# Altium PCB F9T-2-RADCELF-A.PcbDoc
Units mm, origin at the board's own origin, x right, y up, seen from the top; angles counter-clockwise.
Board outline 67.17 x 37.33 mm, 2 copper layers (Top Layer, Bottom Layer), stack 1.581 mm thick; 13 components, 9 nets, 182 pads, 126 vias.
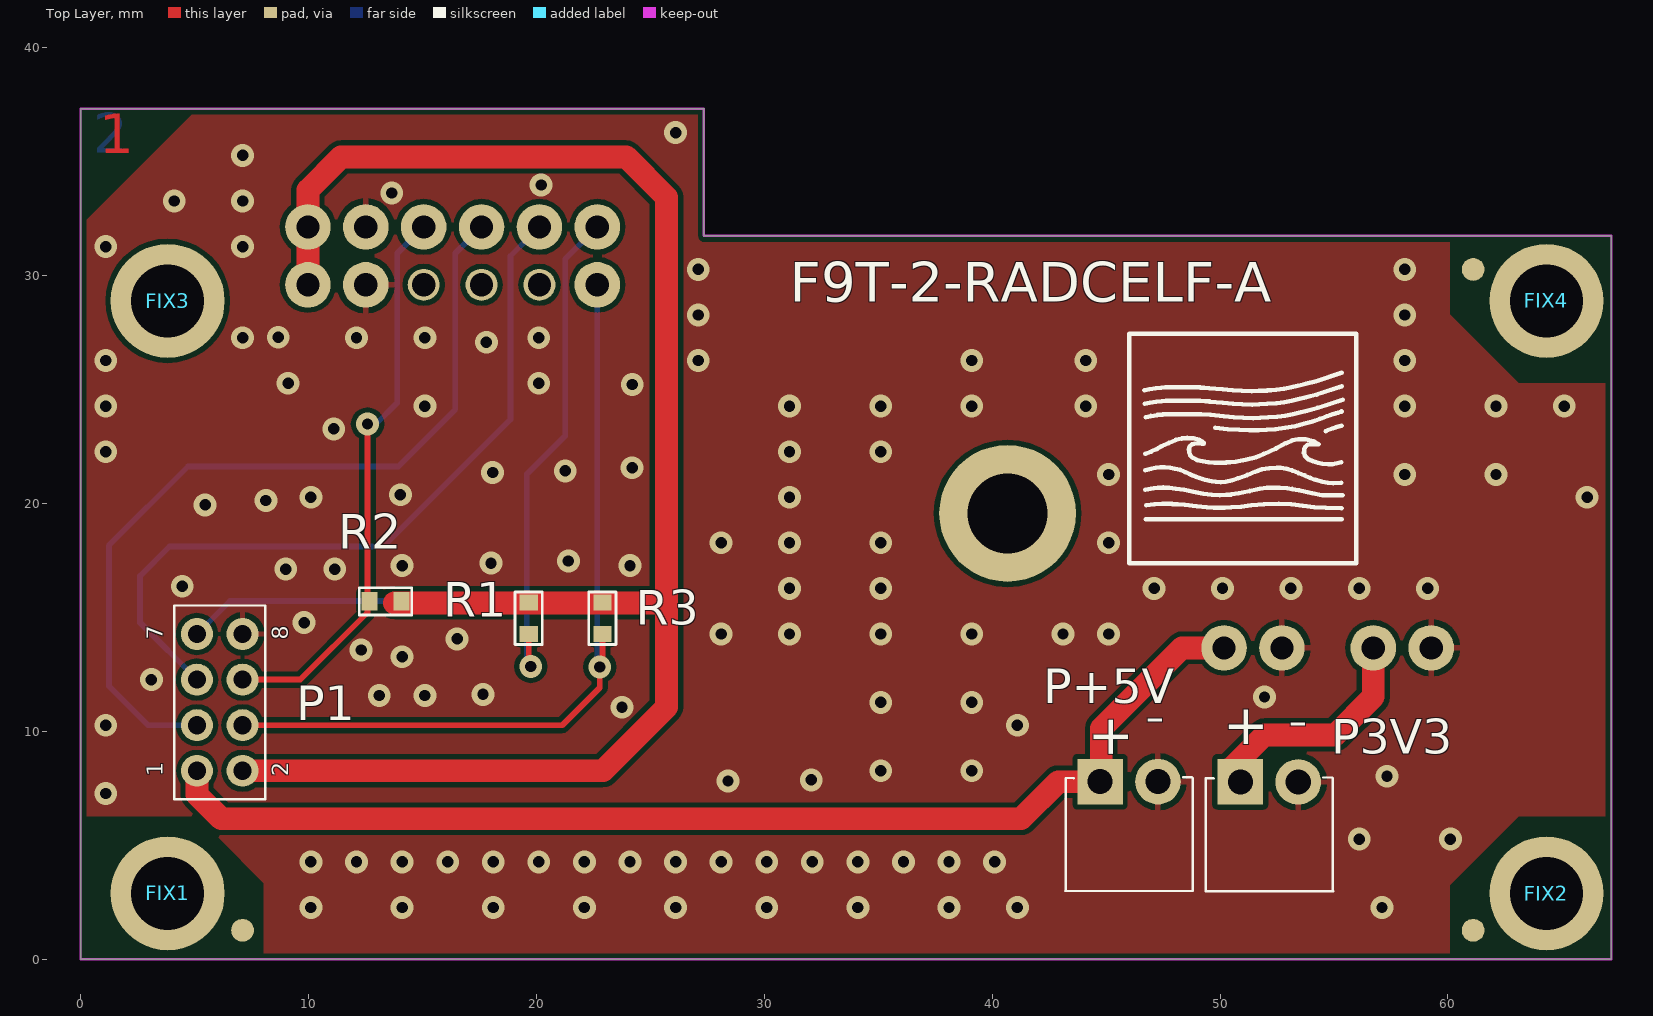
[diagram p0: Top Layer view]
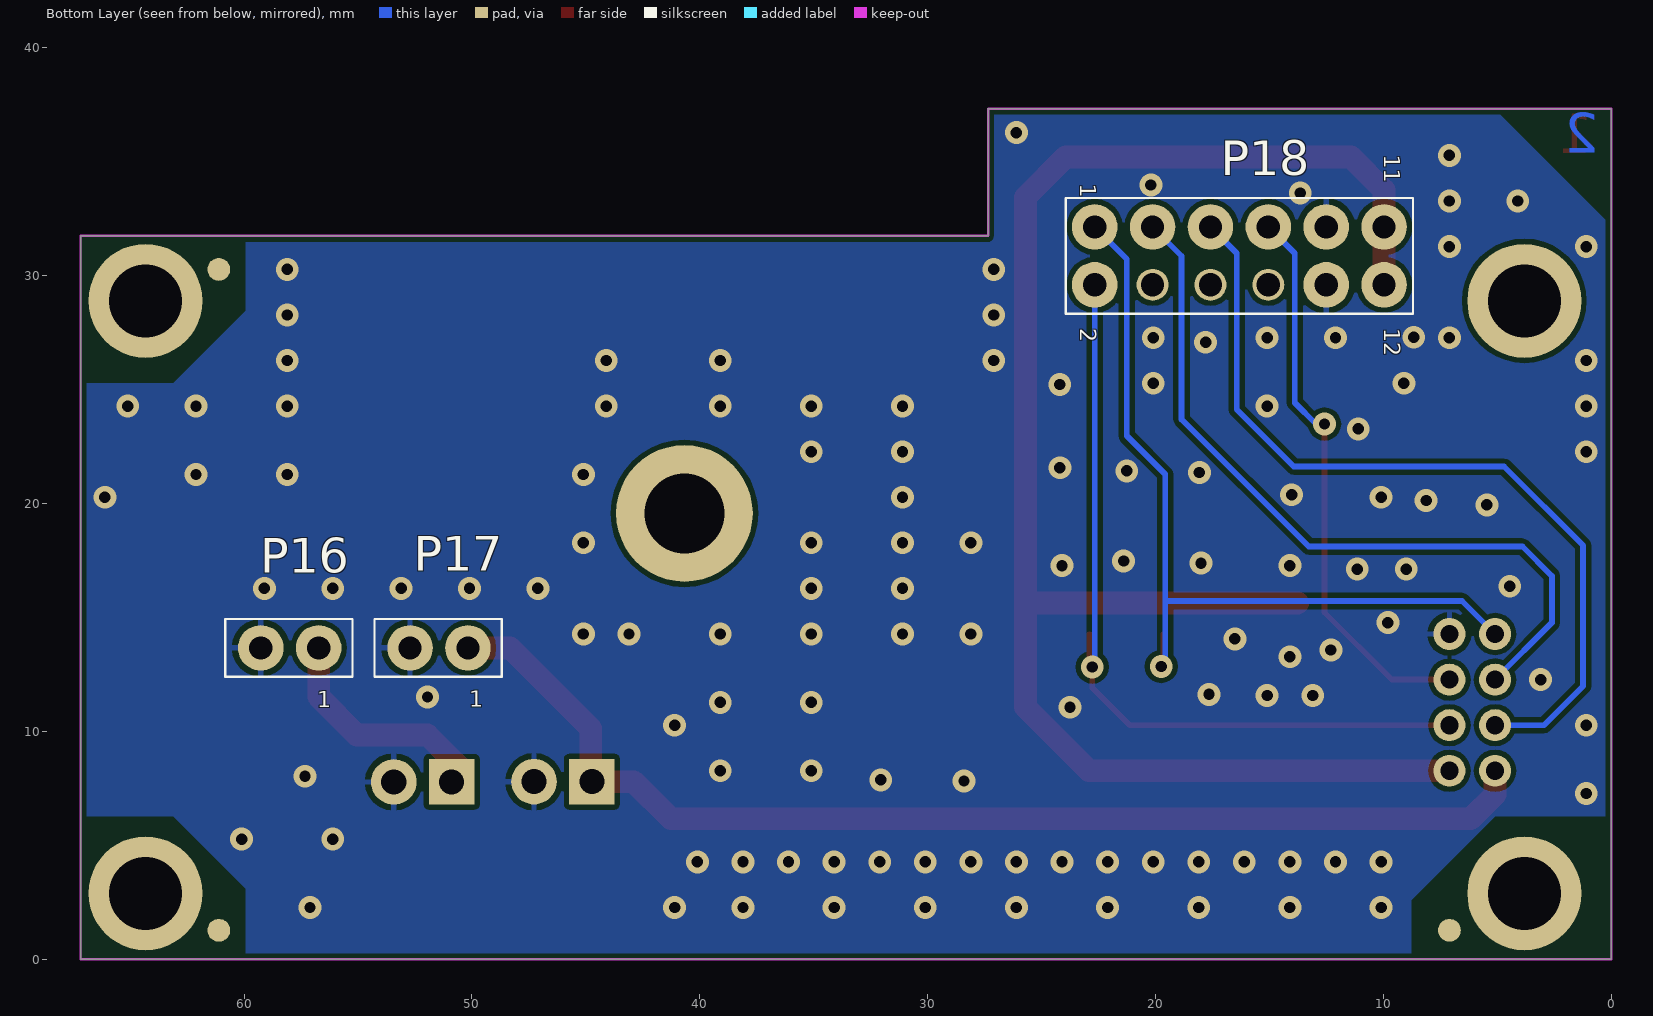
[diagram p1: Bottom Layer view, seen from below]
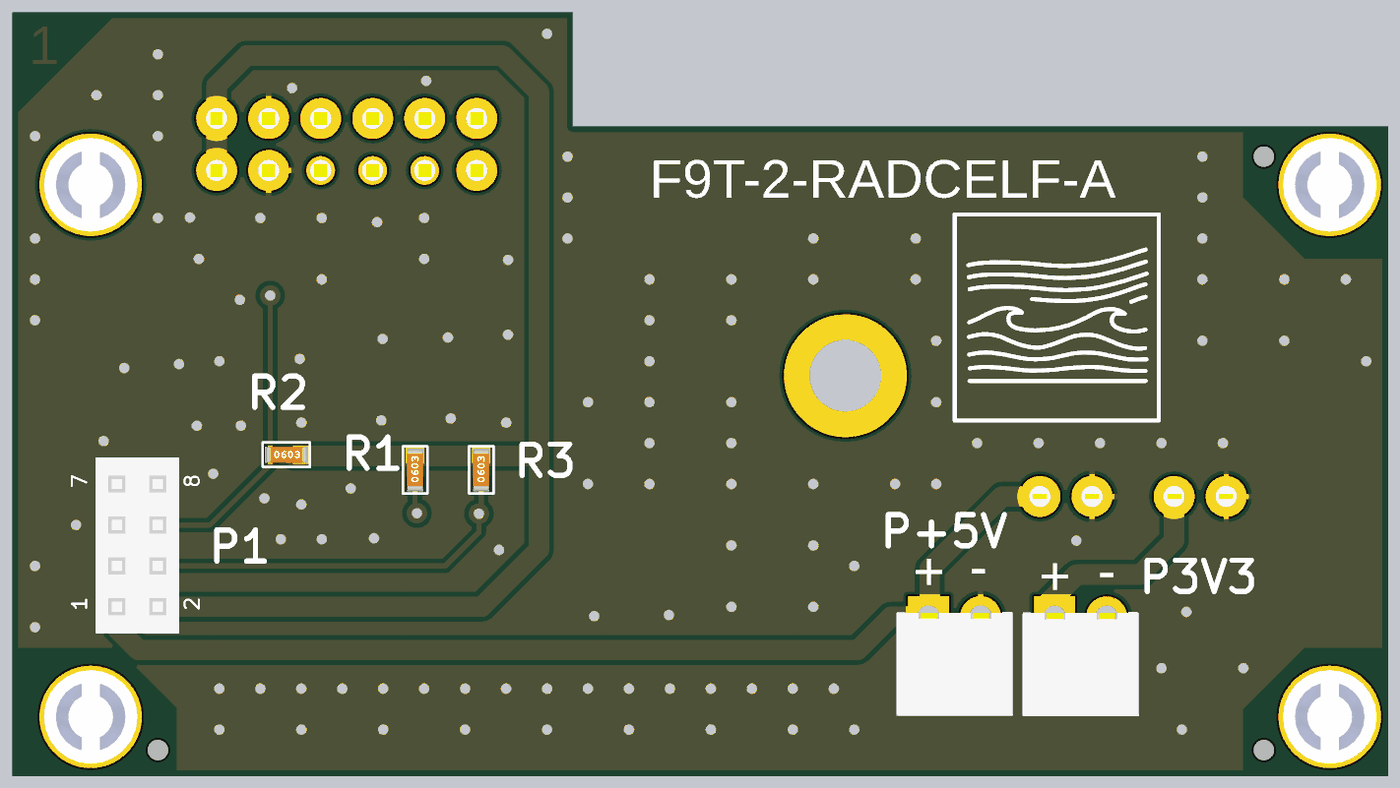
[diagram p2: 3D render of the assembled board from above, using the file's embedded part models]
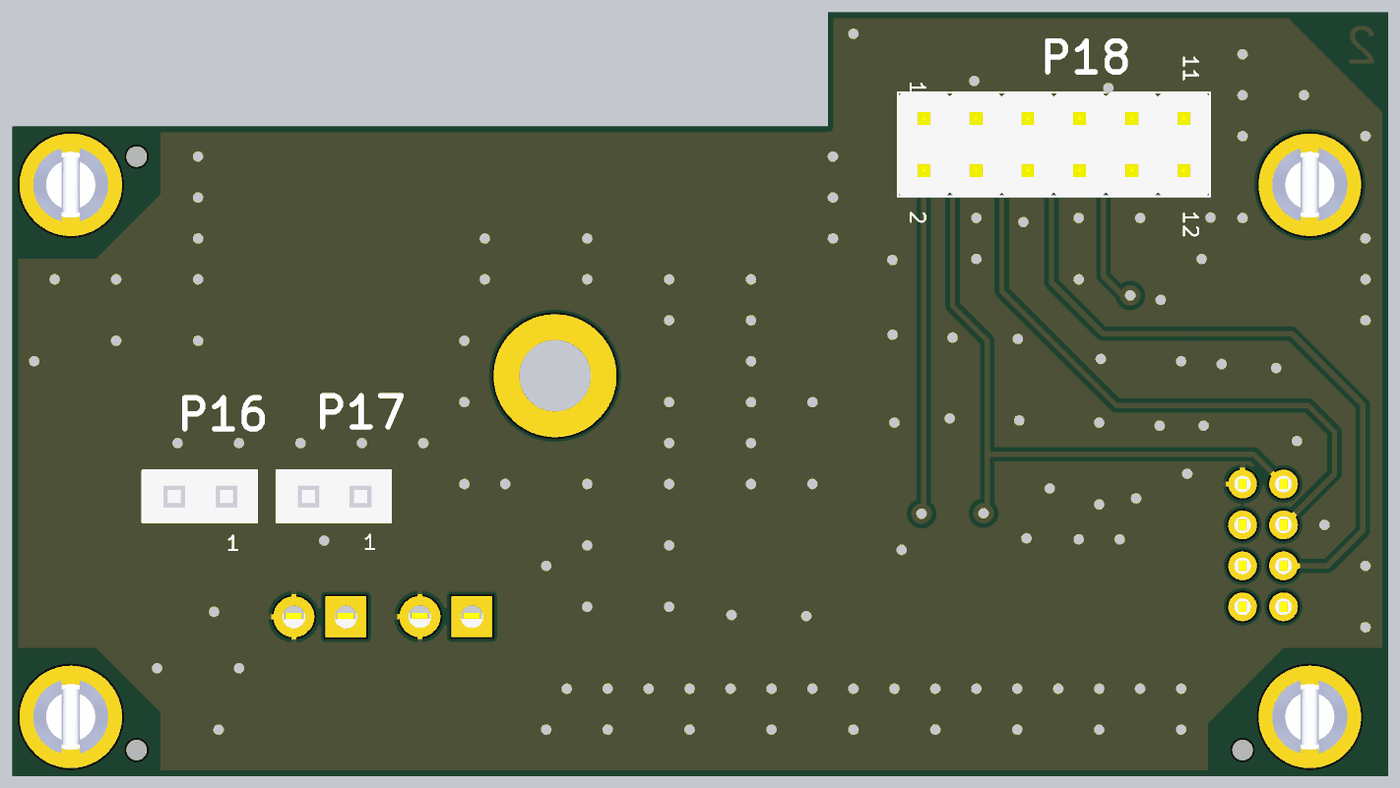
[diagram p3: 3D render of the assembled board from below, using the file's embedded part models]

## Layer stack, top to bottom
Top Solder: solder mask 0.0102, Solder Resist, Dk 3.5
Top Layer: signal copper 0.0356
Dielectric 1: dielectric 1.51, FR-4, Dk 4.8
Bottom Layer: signal copper 0.0356
Bottom Solder: solder mask 0.0102, Solder Resist, Dk 3.5

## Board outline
0,0 0,37.325 27.349,37.325 27.349,31.766 27.366,31.749 67.174,31.749 67.174,0

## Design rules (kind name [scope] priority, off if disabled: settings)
Clearance Clearance_1 [All] p1: gap=0.22 ignorepadtopadclearanceinfootprint=FALSE except(0: Arc-Hole Track-Hole SMDPad-Hole THPad-Hole Via-Hole Fill-Hole Poly-Hole Region-Hole Text-Hole)
Clearance [OnLayer('Keep-Out Layer')] p2: gap=0.4 ignorepadtopadclearanceinfootprint=FALSE except(0: Arc-Hole Track-Hole SMDPad-Hole THPad-Hole Via-Hole Fill-Hole Poly-Hole Region-Hole Text-Hole)
ComponentClearance [All] p1 off: gap=0.254 collisioncheckmode=3 verticalgap=0.254 showdistances=FALSE
Height [All] p1 off: minheight=0 maxheight=25.4 prefheight=12.7
HoleSize [All] p1: absolutevalues=TRUE maxlimit=10 minlimit=0.025 maxpercent=80.000 minpercent=20.000
MinimumSolderMaskSliver [All] p1 off: minsoldermaskwidth=0.254
PolygonConnect PolygonConnect_1 [IsVia] p1: connectstyle=Direct reliefconductorwidth=0.254 reliefentries=4 polygonreliefangle="90 Angle" airgapwidth=0.254
PolygonConnect [All] p2: connectstyle=Relief reliefconductorwidth=0.254 reliefentries=4 polygonreliefangle="90 Angle" airgapwidth=0.254
RoutingVias [All] p1: holewidth=0.711 width=1.27 viastyle="Through Hole" minholewidth=0.3 minwidth=0.7 maxholewidth=0.711 maxwidth=1.27
SilkToBoardRegionClearance [All] p1 off:
SilkToSilkClearance [All] p1 off: silktosilkclearance=0.254
SilkToSolderMaskClearance [IsPad] p1 off: minsilkscreentomaskgap=0.254 clearancetoexposedcopper=TRUE
SolderMaskExpansion [All] p1: expansion=0.102
Width [All] p1: maxlimit=10 minlimit=0.254 preferedwidth=0.254 minimp=50.000000 maximp=50.000000 favimp=50.000000
23 further rules are at their usual default settings.

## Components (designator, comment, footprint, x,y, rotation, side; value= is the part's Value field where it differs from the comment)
FIX1 "8882" 8882 3.823,2.896 r0 top
FIX2 "8882" 8882 64.323,2.896 r0 top
FIX3 "8882" 8882 3.823,28.896 r0 top
FIX4 "8882" 8882 64.323,28.896 r0 top
P1 "AF1D-200-08-G-H63" AF1D-200-08-G-H63 5.107,8.276 r90 top
P3V3 "AF1C-02-G-H5" AF1C-02-G-H5 50.889,7.784 r180 top
P16 "F1D-02-G" F1D-02-G 56.725,13.667 r0 bottom
P17 "" F1D-02-G 50.175,13.667 r0 bottom
P18 "A61-12-7-G" A61-12-7-G 16.324,30.868 r270 bottom locked
P+5V "AF1C-02-G-H5" AF1C-02-G-H5 44.735,7.796 r180 top
R1 "4.7K" 0603 19.662,14.966 r90 top
R2 "4.7K" 0603 13.381,15.711 r0 top
R3 "4.7K" 0603 22.895,14.966 r90 top

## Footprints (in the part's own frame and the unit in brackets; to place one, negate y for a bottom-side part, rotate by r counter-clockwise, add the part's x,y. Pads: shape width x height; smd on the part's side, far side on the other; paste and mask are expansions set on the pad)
0603 [mm]
  rect 0.7x0.8 smd mask+0.05: 1(-0.7,0) 2(0.7,0)
  silkscreen extent -1.15,-0.6 1.15,0.6, body extent -1,-0.39 1,0.39, height 0.79
8882 [mm]
  round 5 hole 3.2: FIX(0,0)
  body extent -2.29,-2.29 2.29,2.29, height 13.29
A61-12-7-G [mm]
  round 2 hole 1.02: 1(-1.27,-6.35) 2(1.27,-6.35) 3(-1.27,-3.81) 5(-1.27,-1.27) 7(-1.27,1.27) 9(1.27,3.81) 10(-1.27,3.81) 11(1.27,6.35) 12(-1.27,6.35)
  round 1.4 hole 1.02: 4(1.27,-3.81) 6(1.27,-1.27) 8(1.27,1.27)
  silkscreen extent -2.54,-7.62 2.54,7.62, body extent -2.54,-7.62 2.54,7.62, height 9.54
AF1C-02-G-H5 [mm]
  rect 2x2 hole 1.1: 1(0,0)
  round 2 hole 1.1: 2(-2.54,0)
  silkscreen extent -4.08,-0.19 1.53,4.8, body extent -4.08,-0.19 1.5,4.81, height 2.6
AF1D-200-08-G-H63 [mm]
  round 1.4 hole 0.8: 1(0,0) 2(0,-2) 3(2,0) 4(2,-2) 5(4,0) 6(4,-2) 7(6,0) 8(6,-2)
  silkscreen extent -1.25,-3 7.25,1, body extent -1.2,-3 7.2,1, height 6.35
F1D-02-G [mm]
  round 2 hole 1.02: 1(0,0) 2(2.54,0)
  silkscreen extent -1.49,-1.27 4.1,1.27, body extent -1.52,-1.27 4.06,1.27, height 5

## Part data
FIX1 FIX2 FIX3 FIX4: library part CON1, "Connector", Manufacturer 1=KEYSTONE
P1: library part CON8, "Connector", Manufacturer 1=ANTELEC
P3V3 P16 P+5V: library part CON2, "Connector", Manufacturer 1=ANTELEC
P17: library part CON2, "Connector", Manufacturer 1=ANTELEC, Manufacturer Part Number 1=F1D-02-G
P18: library part CON12, "Connector", Manufacturer 1=ANTELEC
R1 R2 R3: library part 0805R, "RES SMD 4.7K 1% 1/5W 0603"

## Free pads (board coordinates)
  rect 0.813x0.813 on Mech16: 1(9.212,25.417) 1(10.736,25.417) 1(13.464,25.468) 1(14.988,25.468) 1(18.561,19.268) 1(20.085,19.268) 1(22.813,19.316) 1(24.337,19.316) 1(25.912,29.766) 1(25.912,31.267) 1(25.912,32.768) 1(27.436,29.766) 1(27.436,31.267) 1(27.436,32.768) 1(27.624,26.055) 1(27.624,27.579) 1(35.112,21.468) 1(35.112,22.966) 1(36.062,30.017) 1(36.636,21.468) 1(36.636,22.966) 1(37.586,30.017) 1(39.062,25.217) 1(40.586,25.217)
  rect 1.499x0.45 on Mech16: 1(9.224,19.593) 1(9.224,20.241) 1(9.224,20.891) 1(9.224,21.541) 1(9.224,22.192) 1(9.224,22.842) 1(9.224,23.492) 1(9.224,24.142) 1(15.026,19.593) 1(15.026,20.241) 1(15.026,20.891) 1(15.026,21.541) 1(15.026,22.192) 1(15.026,22.842) 1(15.026,23.492) 1(15.026,24.142) 1(18.523,20.591) 1(18.523,21.242) 1(18.523,21.892) 1(18.523,22.542) 1(18.523,23.192) 1(18.523,23.843) 1(18.523,24.493) 1(18.523,25.143) 1(24.325,20.591) 1(24.325,21.242) 1(24.325,21.892) 1(24.325,22.542) 1(24.325,23.192) 1(24.325,23.843) 1(24.325,24.493) 1(24.325,25.143)
  rect 1.016x1.999 on Mech16: 1(9.974,27.967) 1(9.974,33.766) 1(12.514,27.967) 1(12.514,33.766) 1(15.054,27.967) 1(15.054,33.766) 1(17.594,27.967) 1(17.594,33.766) 1(20.134,27.967) 1(20.134,33.766) 1(22.674,27.967) 1(22.674,33.766)
  round 0.991 on Mech16: 1(11.244,30.868) 1(16.324,30.868) 1(21.404,30.868)
  rect 1.016x1.016 on Mech16: 1(25.584,34.414) 1(25.584,36.319) 1(31.284,21.214) 1(31.284,23.121)
  rect 1.372x1.016 on Mech16: 1(27.616,35.367) 1(33.316,22.166)
  rect 0.399x0.95 on Mech16: 1(29.074,27.518) 1(29.074,29.718) 1(29.725,27.518) 1(29.725,29.718) 1(30.375,27.518) 1(30.375,29.718) 1(39.173,27.416) 1(39.173,29.616) 1(39.824,27.416) 1(39.824,29.616) 1(40.474,27.416) 1(40.474,29.616)
  round 2.54 on Mech16: 1(31.284,33.177) 1(31.284,38.257) 1(33.824,35.717) 1(36.364,33.177) 1(36.364,38.257) 1(41.383,33.078) 1(41.383,38.158) 1(43.923,35.618) 1(46.463,33.078) 1(46.463,38.158) 1(49.585,33.078) 1(49.585,38.158) 1(52.125,35.618) 1(54.665,33.078) 1(54.665,38.158) 1(58.084,33.078) 1(58.084,38.158) 1(60.624,35.618) 1(63.164,33.078) 1(63.164,38.158)
  rect 1.049x2.2 on Mech16: 1(32.348,26.517) 1(35.3,26.517) 1(42.45,26.418) 1(45.399,26.418) 1(50.649,26.418) 1(53.601,26.418) 1(59.151,26.418) 1(62.1,26.418)
  rect 1.148x1.798 on Mech16: 1(33.674,17.767) 1(36.674,17.767)
  rect 0.998x1.049 on Mech16: 1(33.824,28.041) 1(43.923,27.942) 1(52.125,27.942) 1(60.624,27.942)
  rect 1.016x0.864 on Mech16: 1(33.824,29.806) 1(33.824,31.229) 1(43.923,29.705) 1(43.923,31.127) 1(52.125,29.705) 1(52.125,31.127) 1(60.624,29.705) 1(60.624,31.127)
  round 5.791 on Mech16: 1(40.675,19.568)
  rect 1.524x1.524 on Mech16: 1(50.174,13.667) 1(56.725,13.667)
  round 1.524 on Mech16: 1(52.714,13.667) 1(59.265,13.667)
  round 3.198 on Mech16: 1(63.674,14.066)
  round 6 hole 3.5: fix(40.675,19.567)
  round 1 smd mask+0.1: MIRE(7.107,1.276) MIRE(61.107,1.276) MIRE(61.107,30.276)
  round 1 smd far side mask+0.1: MIRE(7.107,1.276) MIRE(61.107,1.276) MIRE(61.107,30.276)

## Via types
v1: diameter 1, hole 0.5, Top Layer to Bottom Layer, 126 vias

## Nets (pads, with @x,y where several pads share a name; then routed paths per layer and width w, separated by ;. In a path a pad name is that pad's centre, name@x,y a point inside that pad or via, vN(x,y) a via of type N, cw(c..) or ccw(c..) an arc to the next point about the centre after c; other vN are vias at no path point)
0VD: P1.8 P3V3.2 P16.2 P17.2 P18.9 P18.10 P+5V.2
  other v1: 10.107,2.276 14.107,2.276 18.107,2.276 22.107,2.276 26.107,2.276 30.107,2.276 34.107,2.276 38.107,2.276 41.107,2.276 57.107,2.276 10.107,4.276 12.107,4.276 14.107,4.276 16.107,4.276 18.107,4.276 20.107,4.276 22.107,4.276 24.107,4.276 26.107,4.276 28.107,4.276 30.107,4.276 32.107,4.276 34.107,4.276 36.107,4.276 38.107,4.276 40.107,4.276 56.107,5.276 60.107,5.276 1.107,7.276 28.407,7.826 32.057,7.876 57.325,8.03 35.107,8.276 39.107,8.276 1.107,10.276 41.107,10.276 23.756,11.058 35.107,11.276 39.107,11.276 51.949,11.511 13.107,11.576 15.107,11.576 17.657,11.626 3.107,12.276 14.107,13.276 12.307,13.576 16.521,14.059 28.107,14.276 31.107,14.276 35.107,14.276 39.107,14.276 43.107,14.276 45.107,14.276 9.807,14.776 31.107,16.276 35.107,16.276 47.107,16.276 50.107,16.276 53.107,16.276 56.107,16.276 59.107,16.276 4.457,16.376 9.007,17.126 11.157,17.126 14.107,17.276 24.107,17.276 18.01,17.386 21.407,17.479 28.107,18.276 31.107,18.276 35.107,18.276 45.107,18.276 5.465,19.942 8.133,20.135 10.107,20.276 31.107,20.276 66.107,20.276 14.032,20.387 45.107,21.276 58.107,21.276 62.107,21.276 18.08,21.364 21.267,21.434 24.198,21.573 1.107,22.276 31.107,22.276 35.107,22.276 11.107,23.276 1.107,24.276 15.107,24.276 31.107,24.276 35.107,24.276 39.107,24.276 44.107,24.276 58.107,24.276 62.107,24.276 65.107,24.276 24.207,25.226 9.107,25.276 20.107,25.276 1.107,26.276 27.107,26.276 39.107,26.276 44.107,26.276 58.107,26.276 17.807,27.076 7.107,27.276 12.107,27.276 15.107,27.276 20.107,27.276 8.67,27.297 27.107,28.276 58.107,28.276 27.107,30.276 58.107,30.276 1.107,31.276 7.107,31.276 4.107,33.276 7.107,33.276 13.657,33.626 20.207,33.976 7.107,35.276 26.107,36.276
+3V3: P3V3.1 P16.1 | length 10.2
  Top Layer w1: P3V3.1@50.525,7.825 50.525,8.423 51.949,9.848 55.053,9.848 56.725,11.52 P16.1
+5V: P1.1 P17.1 P+5V.1 | length 51
  Top Layer w1: P1.1 5.107,7.228 6.169,6.166 41.27,6.166 42.9,7.796 44.784,7.796 44.784,10.125 48.326,13.667 P17.1
+V_PMOD: P1.2 P18.11 P18.12 R1.2 R2.2 R3.2 | length 75.3
  Top Layer w1: P1.2 22.919,8.276 25.71,11.067 25.71,15.711 ; P18.11 P18.12 9.974,33.753 11.433,35.212 23.94,35.212 25.71,33.442 25.71,15.711 ; R2.2@13.776,15.641 25.641,15.641 25.71,15.711
NetP1_4: P1.4 P18.2 R3.1 | length 35.6
  Top Layer w0.254: P1.4 21.136,10.276 22.779,11.919 v1(22.779,12.826) 22.895,12.943 R3.1 ; P18.2 P18.2@22.723,29.548
  Bottom Layer w0.254: P18.2 22.674,12.931 v1(22.779,12.826)
RXD: P1.5 P18.3 | length 33.6
  Bottom Layer w0.254: P1.5 2.613,14.77 2.613,16.819 3.907,18.113 13.281,18.113 18.862,23.695 18.862,30.866 P18.3
TP1: P1.6 P18.7 R2.1 | length 24.9
  Top Layer w0.254: P1.6 9.643,12.276 12.59,15.223 v1(12.59,23.489)
  Bottom Layer w0.254: v1(12.59,23.489) 12.964,23.489 13.897,24.423 13.897,30.981 P18.7
TP2: P1.7 P18.1 R1.1 | length 37.1
  Top Layer w0.254: R1.1 19.662,12.943 v1(19.755,12.849)
  Bottom Layer w0.254: P1.7 6.555,15.724 19.506,15.724 19.58,15.798 ; v1@19.58,12.849 19.58,15.798 ; P18.1 21.271,30.734 21.271,22.973 19.58,21.283 19.58,15.798
TXD: P1.3 P18.5 | length 36.9
  Bottom Layer w0.254: P1.3 2.955,10.276 1.24,11.99 1.24,18.154 4.709,21.622 13.934,21.622 16.436,24.124 16.436,30.98 P18.5
pads on no net: FIX1.FIX FIX2.FIX FIX3.FIX FIX4.FIX P18.4 P18.6 P18.8

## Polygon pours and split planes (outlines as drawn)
0VD on Bottom Layer "Bottom Layer-No Net" (solid, remove dead copper, pour order 0): -1.893,6.276 5.107,6.276 8.782,2.601 8.782,-0.724 59.931,-0.724 59.931,3.099 62.107,5.276 63.107,6.276 65.107,6.276 67.107,6.276 67.107,25.276 66.107,25.276 63.107,25.276 59.931,28.452 59.931,32.276 28.107,32.276 28.107,33.276 28.107,38.276 27.107,38.276 6.107,38.276 -0.893,31.276
0VD on Top Layer "Bottom Layer-No Net" (solid, remove dead copper, pour order 2): -1.893,6.276 5.107,6.276 8.035,3.347 8.035,-0.724 60.08,-0.724 60.08,3.249 62.107,5.276 63.107,6.276 65.107,6.276 67.107,6.276 67.107,25.276 66.107,25.276 63.107,25.276 60.08,28.303 60.08,32.276 28.107,32.276 28.107,33.276 28.107,38.276 27.107,38.276 6.107,38.276 -0.893,31.276

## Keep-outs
Keep-Out Layer:
  the board outline again, w0.1

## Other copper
Top Layer:
  text "1" at 0.811,34.802 h3
Bottom Layer:
  text "2" at 0.55,34.82 h3

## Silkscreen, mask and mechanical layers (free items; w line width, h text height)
Top Overlay:
  drawing of 222 lines, arcs and shapes, not listed
  text "F9T-2-RADCELF-A" at 31.107,28.276 h3
  text "+" at 43.879,10.756 h3 r270
  text "-" at 46.717,9.313 h3
  text "-" at 52.999,9.127 h3
  text "+" at 50.137,8.871 h3
Mechanical 1:
  text "1" at 23.851,33.503 h1.52
  text "11" at 7.219,33.428 h1.52
  text "2" at 23.964,28.386 h1.52
  text "12" at 6.768,26.805 h1.52
  text "2" at 58.959,15.366 h1.52
  text "2" at 52.524,15.216 h1.52
  text "1" at 49.74,15.065 h1.52
  text "1" at 56.362,15.027 h1.52
  text "2" at 10.098,7.897 h1.52
  text "1" at 0.954,7.784 h1.52
Mechanical 3:
  drawing of 955 lines, arcs and shapes, not listed
Mechanical 5:
  lines w0.127: 26.645,-77.872 26.645,-69.191 ; 65.753,-62.366 183.056,-62.366 ; 65.753,-55.541 183.056,-55.541 ; 65.753,-44.451 183.056,-44.451 ; 65.753,-40.185 183.056,-40.185 ; 65.753,-35.919 183.056,-35.919 ; 65.753,-31.654 183.056,-31.654 ; 89.128,-48.716 89.128,-27.388 ; 106.626,-69.191 106.626,-48.716 ; 146.824,-48.716 146.824,-27.388 ; 165.847,-48.716 165.847,-27.388 ; 183.056,-27.388 26.645,-27.388 ; 26.645,-69.191 183.056,-69.191 ; 26.645,-69.191 65.753,-69.191 ; 26.645,-69.191 26.645,-27.388 ; 26.645,-27.388 65.753,-27.388 ; 65.753,-69.191 65.753,-27.388 ; 65.753,-69.191 65.753,-27.388 ; 65.753,-69.191 183.056,-69.191 ; 65.753,-69.191 65.753,-48.716 ; 65.753,-48.716 183.056,-48.716 ; 65.753,-48.716 183.056,-48.716 ; 164.988,-69.191 164.988,-55.541 ; 164.988,-69.191 183.056,-69.191 ; 164.988,-69.191 164.988,-55.541 ; 164.988,-62.366 164.988,-55.541 ; 164.988,-62.366 183.056,-62.366 ; 164.988,-62.366 164.988,-55.541 ; 164.988,-55.541 183.056,-55.541 ; 164.988,-55.541 183.056,-55.541 ; 183.056,-69.191 183.056,-55.541 ; 183.056,-69.191 183.056,-48.716 ; 183.056,-62.366 183.056,-55.541
  lines w0.5: -47.659,-77.86 26.665,-77.86 183.065,-77.86 183.065,80.267 -47.659,80.267 -47.659,-77.86
  text "Indice" at 69.814,-47.307 h1.76
  text "Modification" at 108.783,-47.307 h1.76
  text "Date" at 152.457,-47.307 h1.76
  text "Dessine par" at 168.011,-47.389 h1.5
  text "Edition" at 66.724,-53.318 h1.76
  text ":" at 86.662,-53.318 h1.76
  text "F9T-2-RADCELF" at 110.465,-53.96 h1.8
  text "Dessinateur" at 66.724,-59.329 h1.76
  text "Folio" at 165.863,-59.329 h1.8
  text ":" at 86.662,-59.35 h1.76
  text ":" at 174.332,-59.35 h1.76
  text "1/1" at 176.709,-59.726 h1.76
  text "RONVEL" at 89.73,-59.841 h1.95
  text ":" at 86.662,-65.943 h1.76
  text "Date" at 66.724,-65.994 h1.76
  text "Ind A" at 165.863,-65.994 h1.95
  text "06-04-21" at 88.765,-66.96 h1.8
Mechanical 6:
  lines w0.127: -47.662,-44.468 69.64,-44.468 ; -47.662,-40.202 69.64,-40.202 ; -47.662,-35.936 69.64,-35.936 ; -47.662,-31.671 69.64,-31.671 ; -47.662,-27.405 108.748,-27.405 ; -30.453,-48.733 -30.453,-27.405 ; -11.431,-48.733 -11.431,-27.405 ; 28.767,-69.208 28.767,-48.733 ; 46.265,-48.733 46.265,-27.405 ; 69.64,-62.383 -47.662,-62.383 ; 69.64,-55.558 -47.662,-55.558 ; 108.748,-77.889 108.748,-69.208 ; -47.662,-69.208 69.64,-69.208 ; -47.662,-69.208 -47.662,-48.733 ; -47.662,-69.208 -29.595,-69.208 ; -47.662,-69.208 -47.662,-55.558 ; -47.662,-69.208 108.748,-69.208 ; -47.662,-62.383 -29.595,-62.383 ; -47.662,-62.383 -47.662,-55.558 ; -47.662,-55.558 -29.595,-55.558 ; -47.662,-55.558 -29.595,-55.558 ; -47.662,-48.733 69.64,-48.733 ; -47.662,-48.733 69.64,-48.733 ; -29.595,-69.208 -29.595,-55.558 ; -29.595,-69.208 -29.595,-55.558 ; -29.595,-62.383 -29.595,-55.558 ; -29.595,-62.383 -29.595,-55.558 ; 69.64,-69.208 69.64,-48.733 ; 69.64,-69.208 108.748,-69.208 ; 69.64,-69.208 69.64,-27.405 ; 69.64,-69.208 69.64,-27.405 ; 69.64,-27.405 108.748,-27.405 ; 108.748,-69.208 108.748,-27.405
  lines w0.5: -47.672,-77.877 -47.672,80.251 183.053,80.251 183.053,-77.877 108.728,-77.877 -47.672,-77.877
  text "Date" at -17.064,-47.324 h1.76
  text "Modification" at 26.61,-47.324 h1.76
  text "Indice" at 65.579,-47.324 h1.76
  text "Dessine par" at -32.618,-47.406 h1.5
  text ":" at 48.731,-53.335 h1.76
  text "Edition" at 68.67,-53.335 h1.76
  text "F9T-2-RADCELF" at 24.928,-53.977 h1.8
  text "Folio" at -30.47,-59.346 h1.8
  text "Dessinateur" at 68.67,-59.346 h1.76
  text ":" at -38.939,-59.367 h1.76
  text ":" at 48.731,-59.367 h1.76
  text "1/1" at -41.316,-59.743 h1.76
  text "RONVEL" at 45.663,-59.858 h1.95
  text "PLAN DE CABLAGE BOTTOM" at 20.928,-60.477 h4
  text ":" at 48.731,-65.96 h1.76
  text "Ind A" at -30.47,-66.011 h1.95
  text "Date" at 68.67,-66.011 h1.76
  text "06-04-21" at 46.628,-66.977 h1.8
Mechanical 7:
  text "PLAN DE CABLAGE TOP" at 114.465,-60.46 h4
Mechanical 9:
  text "PLAN DE PERCAGE" at 120.065,-60.36 h4
Mechanical 14:
  drawing of 534 lines, arcs and shapes, not listed
Drill Drawing:
  lines w0.1: 79.58,-18.902 177.65,-18.902 ; 79.58,1.593 177.65,1.593 ; 91.716,-22.318 91.716,5.009 ; 104.892,-22.318 104.892,5.009 ; 131.272,-22.318 131.272,5.009 ; 142.383,-22.318 142.383,5.009 ; 158.685,-22.318 158.685,5.009 ; 79.58,-22.318 177.65,-22.318 177.65,5.009 79.58,5.009 79.58,-22.318 ; 80.902,-11.046 81.661,-10.666 82.42,-11.046 82.04,-10.287 82.42,-9.528 81.661,-9.907 80.902,-9.528 81.281,-10.287 80.902,-11.046 ; 80.902,-6.112 82.42,-6.112 81.661,-7.63 80.902,-6.112 ; 80.902,-3.835 81.281,-3.835 81.661,-4.214 82.04,-3.835 82.42,-3.835 82.04,-3.455 82.42,-3.075 82.04,-3.075 81.661,-2.696 81.281,-3.075 80.902,-3.075 81.281,-3.455 80.902,-3.835 ; 80.902,-0.798 82.42,-0.798 82.42,0.72 80.902,0.72 80.902,-0.798 ; 81.205,-10.742 81.661,-10.514 82.116,-10.742 81.888,-10.287 82.116,-9.831 81.661,-10.059 81.205,-9.831 81.433,-10.287 81.205,-10.742 ; 81.205,-6.415 82.116,-6.415 81.661,-7.326 81.205,-6.415 ; 81.205,-3.683 81.433,-3.683 81.661,-3.91 81.888,-3.683 82.116,-3.683 81.888,-3.455 82.116,-3.227 81.888,-3.227 81.661,-3 81.433,-3.227 81.205,-3.227 81.433,-3.455 81.205,-3.683 ; 81.205,-0.495 82.116,-0.495 82.116,0.416 81.205,0.416 81.205,-0.495
  text "MATIERE FR4 16/10eme / CUIVRE 35 microns / Finition NiAu / Techno double face / VERNIS SELECTIF VERT 2 FACES / SERIGRAPHIE BLANCHE 2 FACES" at 99.173,33.615 h4
  text "Symbol" at 81.629,2.618 h1.64
  text "Count" at 92.74,2.618 h1.64
  text "Hole Size" at 105.917,2.618 h1.64
  text "Plated" at 132.297,2.618 h1.64
  text "Hole Type" at 143.408,2.618 h1.64
  text "Technology" at 159.709,2.618 h1.64
  text "1" at 92.74,-0.798 h1.37
  text "3,500mm (137,80mil)" at 105.917,-0.798 h1.37
  text "PTH" at 132.297,-0.798 h1.37
  text "Round" at 143.408,-0.798 h1.37
  text "c600h350" at 159.709,-0.798 h1.37
  text "4" at 92.74,-4.214 h1.37
  text "1,100mm (43,31mil)" at 105.917,-4.214 h1.37
  text "PTH" at 132.297,-4.214 h1.37
  text "Round" at 143.408,-4.214 h1.37
  text "(Mixed)" at 159.709,-4.214 h1.37
  text "4" at 92.74,-7.63 h1.37
  text "3,200mm (125,98mil)" at 105.917,-7.63 h1.37
  text "PTH" at 132.297,-7.63 h1.37
  text "Round" at 143.408,-7.63 h1.37
  text "c500h320" at 159.709,-7.63 h1.37
  text "8" at 92.74,-11.046 h1.37
  text "0,800mm (31,50mil)" at 105.917,-11.046 h1.37
  text "PTH" at 132.297,-11.046 h1.37
  text "Round" at 143.408,-11.046 h1.37
  text "c140h80" at 159.709,-11.046 h1.37
  text "16" at 92.74,-14.461 h1.37
  text "1,020mm (40,16mil)" at 105.917,-14.461 h1.37
  text "PTH" at 132.297,-14.461 h1.37
  text "Round" at 143.408,-14.461 h1.37
  text "(Mixed)" at 159.709,-14.461 h1.37
  text "A" at 81.055,-14.561 h1.52
  text "126" at 92.74,-17.877 h1.37
  text "0,500mm (19,69mil)" at 105.917,-17.877 h1.37
  text "PTH" at 132.297,-17.877 h1.37
  text "Round" at 143.408,-17.877 h1.37
  text "v100h50m50" at 159.709,-17.877 h1.37
  text "C" at 81.055,-17.977 h1.52
  text "159 Total" at 92.74,-21.293 h1.37
Mechanical 30:
  lines w0.05: 59.265,13.667 59.265,14.192

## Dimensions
0,0 to 67.174,0 on Drill Drawing
0,0 to -0.002,37.325 on Drill Drawing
